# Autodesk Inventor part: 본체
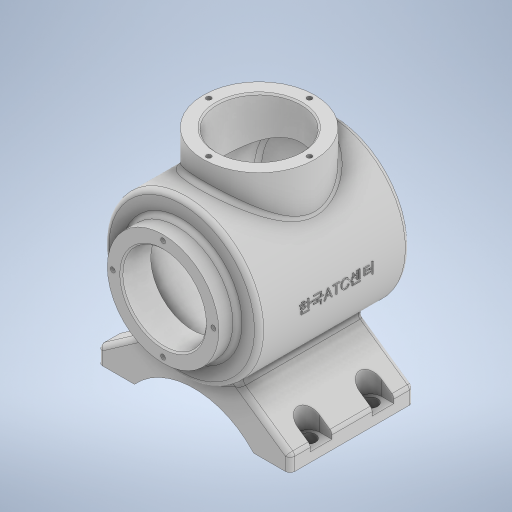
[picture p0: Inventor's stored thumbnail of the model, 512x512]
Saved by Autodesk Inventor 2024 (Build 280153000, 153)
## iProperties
Created: 2023-08
Part Number: 본체
Material: 일반
Document SubType Name: Modeling
Designer: Owner
Density: 1 g/cm^3
Appearance: 기본값
Author: Owner
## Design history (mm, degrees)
sketch "스케치1"
  geometry: L1 (0, 60)-(0, -60); L2 (0, 60)-(36, 60); L3 (36, 60)-(36, 48); L4 (36, 48)-(50, 48); L5 (50, 48)-(50, -48.336); L6 (27, 60)-(27, 41); L7 (27, 41)-(43, 41); L8 (43, 41)-(43, -43.887); A1 r 113 centre (0, 53) between (0, -60) and (50, -48.336); A2 r 106 centre (0, 53) between (0, -53) and (43, -43.887); 2 further points
  constraints: 16 end point, 6 perpendicular, 4 point on circle, 3 point on line, 2 centre point, 1 coincident, 1 horizontal, 1 midpoint, 1 vertical
  dimensions: "d0" = 120 distance of L1.start L1.end; "d1" = 72 diameter of L3 L1; "d2" = 100 diameter of L5 L1; "d3" = 113 radius of A1; "d5" = 108 distance from line of L1.end L4; "d6" = 7 radial gap between concentric circles of A1 A2; "d7" = 54 diameter of L6 L1; "d8" = 86 diameter of L8 L1; "d9" = 19 distance of L6.start L6.end
revolve "회전1" sketch "스케치1" stored, may be unused: angle "d10" = 90 deg
node "작업 평면1"
sketch "스케치2"
  geometry: L1 (62, -40)-(-62, -40); L2 (-62, -40)-(-62, 40); L3 (-62, 40)-(62, 40); L4 (62, 40)-(62, -40); L5 (62, -40)-(-62, 40); L6 (-62, -40)-(62, 40); 2 further points
  constraints: 12 end point, 2 midpoint, 2 parallel, 1 coincident, 1 horizontal, 1 perpendicular
  dimensions: "d17" = 124 distance of L2.end L3.end; "d18" = 80 distance of L1.end L2.end
extrude "돌출1" join sketch "스케치2" distance "d19" = 10; taper "d20" = 0 deg
sketch "스케치3"
  geometry: L1 (-62, -40)-(62, -40) reference; L2 (-14.332, 40)-(14.332, 40); L3 (14.332, 40)-(14.332, -40); L4 (14.332, -40)-(-14.332, -40); L5 (-14.332, -40)-(-14.332, 40); L6 (-14.332, 40)-(14.332, -40); L7 (14.332, 40)-(-14.332, -40); 3 further points
  constraints: 12 end point, 2 midpoint, 2 parallel, 1 coincident, 1 horizontal, 1 perpendicular, 1 point on line
  dimensions: "d21" = 28.66375 distance of L2.start L2.end
extrude "돌출2" join sketch "스케치3" stored distance "d22" = 10; taper "d23" = 0 deg
sketch "스케치4"
  geometry: L1 (62, -67)-(38.713, -50.694); L2 (62, -77)-(62, -67) reference; 1 further point
  constraints: 2 end point, 1 coincident
  dimensions: "d24" = 55 deg angle of L2 L1
feature "리브1" sketch "스케치4" dims "d25" = 1, "d26" = 80, "d27" = 0, "d28" = 0, "d29" = 1, "d30" = 1
node "작업 평면2"
sketch "스케치6"
  geometry: L1 (62, -40)-(-62, -40) reference; L2 (62, 40)-(62, -40) reference; L3 (54, -27)-(62, -27); L4 (54, -13)-(62, -13); A1 r 7 centre (54, -20) between (54, -13) and (54, -27); 1 further point
  constraints: 4 end point, 2 perpendicular, 2 point on circle, 2 point on line, 2 tangent, 1 centre point
  dimensions: "d32" = 14 diameter of A1; "d33" = 20 distance from line of A1.centre L1; "d34" = 8 distance from line of L2 A1.centre
extrude "돌출3" cut sketch "스케치6" stored distance "d35" = 0; taper "d36" = 0 deg
sketch "스케치7"
  geometry: A1 r 7 centre (54, 20) between (54, 27) and (54, 13) reference; 2 further points
  constraints: 1 coincident
hole "구멍1" sketch "스케치7" at (54, 20) diameter "d37" = 9; stored, may be unused: countersink angle "d41" = 90 deg, drill point angle "d43" = 118 deg; dims "d38" = 8, "d39" = 4, "d40" = 2, "d42" = 10
sketch "스케치8"
  geometry: L1 (0, 0)-(124, 0) reference; A1 r 52.096 centre (62, -35.096) between (100.5, 0) and (23.5, 0); 2 further points
  constraints: 3 point on circle, 2 point on line, 1 centre point, 1 vertical alignment
  dimensions: "d44" = 77 distance of A1.start A1.end; "d45" = 17 distance from line of L1 point (62, 17)
extrude "돌출4" cut sketch "스케치8" extent not by distance; stored distance "d46" = 10; taper "d47" = 0 deg
node "작업 평면3"
sketch "스케치9"
  geometry: L1 (-36, 60)-(36, 60) reference; C1 r 36 at (0, -2); 1 further point
  constraints: 1 centre point, 1 vertical alignment
  dimensions: "d49" = 72 diameter of C1; "d50" = 62 distance from line of C1.centre L1
extrude "돌출5" join sketch "스케치9" stored distance "d51" = 10; taper "d52" = 0 deg
sketch "스케치10"
  geometry: C1 r 36 at (0, 0) reference; C2 r 27 at (0, 0); 1 further point
  constraints: 1 centre point, 1 coincident
  dimensions: "d53" = 54 diameter of C2
extrude "돌출6" cut sketch "스케치10" stored distance "d54" = 10; taper "d55" = 0 deg
sketch "스케치11"
  geometry: C1 r 27 at (0, 0) reference; 2 further points
  constraints: 1 vertical alignment
  dimensions: "d56" = 32.5 distance of C1.centre point (0, 32.5)
hole "구멍2" sketch "스케치11" at (0, 32.5) diameter "d57" = 3.242; stored, may be unused: countersink angle "d61" = 90 deg, drill point angle "d63" = 118 deg; dims "d58" = 8, "d59" = 4, "d60" = 2, "d62" = 10
sketch "스케치12"
  geometry: 2 further points
  constraints: 1 vertical alignment
  dimensions: "d67" = 32.5 distance of point (0, 0) point (0, 32.5)
hole "구멍3" sketch "스케치12" at (0, 32.5) diameter "d68" = 3.242; stored, may be unused: countersink angle "d72" = 90 deg, drill point angle "d74" = 118 deg; dims "d69" = 8, "d70" = 4, "d71" = 2, "d73" = 10
fillet "모깎기1" dims "d78" = 3
fillet "모깎기2" dims "d79" = 3
fillet "모깎기3" dims "d80" = 3
fillet "모깎기4" dims "d81" = 3
chamfer "모따기1" distance "d82" = 1; stored, may be unused: second distance "d83" = 2, angle "d84" = 45 deg
node "작업 평면4"
sketch "스케치13"
  geometry: L1 (-36, 60.168)-(36, 60.168) reference; 2 further points
  constraints: 1 vertical alignment, 1 other
  dimensions: "d85" = 62 distance from line of point (0, -1.832) L1
feature "엠보싱1" sketch "스케치13" dims "d0" = 120, "d1" = 72, "d2" = 100, "d3" = 113, "d5" = 108, "d6" = 7, "d7" = 54, "d8" = 86, "d9" = 19, "d86" = 0.5, "d87" = 0
feature "̿耀́耀̓耀ͅ耀͇耀͉耀͋耀͍耀" dims "d0" = 120, "d1" = 72, "d2" = 100, "d3" = 113, "d5" = 108, "d6" = 7, "d7" = 54, "d8" = 86, "d9" = 19, "d10" = 90 deg, "d11" = -77, "d17" = 124, "d18" = 80, "d19" = 10, "d20" = 0, "d21" = 28.66375, "d22" = 10, "d23" = 0, "d24" = 55 deg, "d25" = 1, "d26" = 80, "d27" = 0, "d28" = 0, "d29" = 1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
node "솔리드1"
mirror "미러1"
mirror "미러2"
mirror "미러3"
pattern_circular "원형 패턴1" dims angle "d65" = 360 deg
pattern_circular "원형 패턴2" dims angle "d76" = 360 deg
feature "A9D066F2-1C7D-4E18-AEED-F7BC21143FA4" dims "d37" = 9, "d38" = 8, "d39" = 4, "d40" = 2, "d41" = 90 deg, "d42" = 10, "d43" = 118 deg
